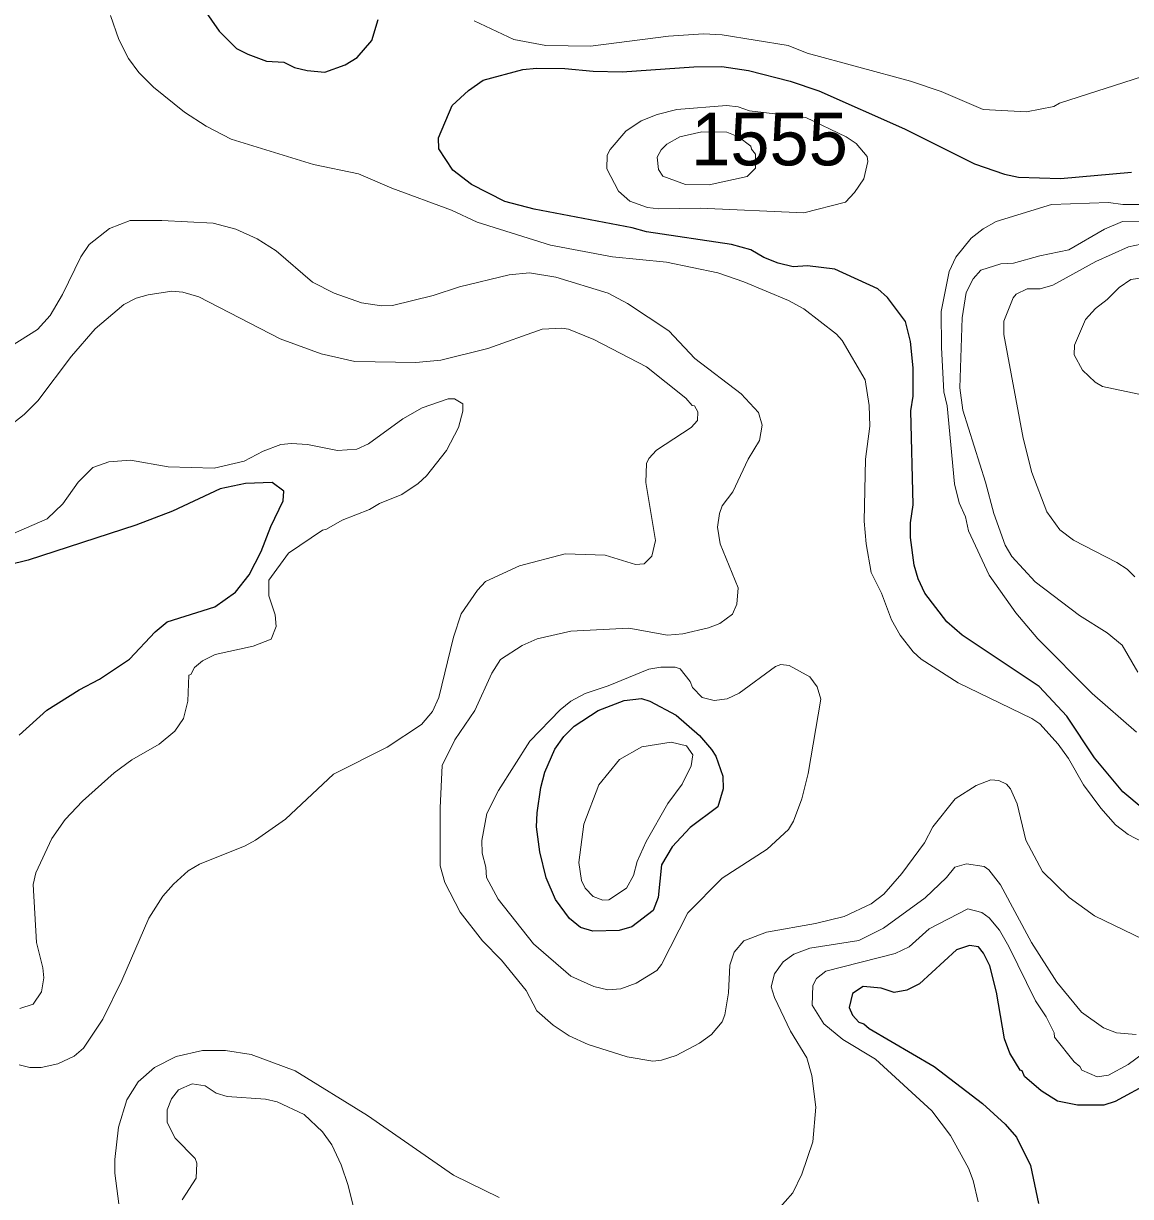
# Model space of a CAD drawing. Extents: x 598.3 to 623.2, y 6902.2 to 6930.1.
# Drawn here: x 605.691 to 607.371, y 6908.921 to 6910.701 of the extents above; entities that cross this region are included whole.
import ezdxf

# ---------------------------------------------------------------- set-up
doc = ezdxf.new("R2010")
doc.units = 0
doc.header["$LTSCALE"] = 0.032
doc.layers.add('1', color=7, linetype='Continuous', lineweight=25)
doc.layers.add('2', color=7, linetype='Continuous', lineweight=13)
doc.layers.add('21', color=7, linetype='Continuous')

msp = doc.modelspace()

# ---------------------------------------------------------------- linework, layer by layer
at = {"layer": '1'}
for points in [[(605.9446, 6910.7518), (605.9877, 6910.6896), (606.0141, 6910.6633), (606.0311, 6910.6543), (606.0598, 6910.644), (606.0857, 6910.6423), (606.1021, 6910.6343), (606.1212, 6910.6295), (606.1482, 6910.627), (606.1788, 6910.6382), (606.1974, 6910.6495), (606.2193, 6910.675), (606.2292, 6910.7071)], [(607.3906, 6909.5092), (607.3598, 6909.5352), (607.3165, 6909.5866), (607.2744, 6909.6497), (607.2324, 6909.695), (607.1155, 6909.7729), (607.0923, 6909.7932), (607.0588, 6909.8364), (607.0487, 6909.8581), (607.0429, 6909.8791), (607.0371, 6909.9212), (607.0371, 6909.9432), (607.0412, 6909.9705), (607.0379, 6910.1132), (607.0411, 6910.1353), (607.0411, 6910.1784), (607.0372, 6910.2184), (607.0297, 6910.2489), (607.0024, 6910.2851), (606.9877, 6910.2983), (606.9226, 6910.3283), (606.8811, 6910.3331), (606.8591, 6910.3317), (606.8364, 6910.3374), (606.8147, 6910.346), (606.795, 6910.3574), (606.7656, 6910.3656), (606.6364, 6910.3849), (606.6146, 6910.3908), (606.4661, 6910.419), (606.4213, 6910.4308), (606.3709, 6910.4566), (606.3424, 6910.4785), (606.321, 6910.5107), (606.3207, 6910.5274), (606.3413, 6910.5767), (606.3662, 6910.5995), (606.3887, 6910.6148), (606.4486, 6910.631), (606.4693, 6910.6334), (606.5125, 6910.6326), (606.5554, 6910.6285), (606.5998, 6910.6278), (606.7083, 6910.6351), (606.7511, 6910.6357), (606.7915, 6910.6295), (606.8546, 6910.6133), (606.8979, 6910.5989), (607.0284, 6910.541), (607.1343, 6910.488), (607.18, 6910.4724), (607.2011, 6910.4676), (607.2652, 6910.4659), (607.3727, 6910.4756)], [(605.6841, 6909.6213), (605.7264, 6909.6591), (605.7753, 6909.6897), (605.8061, 6909.7059), (605.8518, 6909.7366), (605.8907, 6909.7777), (605.9089, 6909.7928), (605.981, 6909.816), (606.0124, 6909.8379), (606.0331, 6909.8642), (606.0514, 6909.8996), (606.0662, 6909.9375), (606.085, 6909.9767), (606.0859, 6909.9912), (606.068, 6910.0045), (606.0279, 6910.0029), (605.9891, 6909.9948), (605.9169, 6909.9612), (605.8612, 6909.9398), (605.6977, 6909.8864), (605.607, 6909.8645)], [(607.4019, 6909.0943), (607.3478, 6909.0649), (607.3306, 6909.0594), (607.2907, 6909.0598), (607.2603, 6909.0656), (607.2356, 6909.0815), (607.2101, 6909.1029), (607.2069, 6909.1115), (607.2038, 6909.1127), (607.1883, 6909.1386), (607.1798, 6909.1601), (607.1677, 6909.2309), (607.1577, 6909.2708), (607.1481, 6909.2903), (607.1403, 6909.2998), (607.1266, 6909.3017), (607.1073, 6909.2951), (607.0511, 6909.2436), (607.0317, 6909.234), (607.0123, 6909.2307), (606.9925, 6909.237), (606.9653, 6909.2395), (606.9491, 6909.2291), (606.944, 6909.2079), (606.949, 6909.1964), (606.9586, 6909.1853), (606.9664, 6909.1829), (606.9746, 6909.1759), (607.0733, 6909.1183), (607.1466, 6909.062), (607.1809, 6909.0308), (607.1983, 6909.0109), (607.2193, 6908.968), (607.2314, 6908.9104)]]:
    msp.add_lwpolyline(points, dxfattribs=at)
msp.add_lwpolyline([(606.4697, 6909.4818), (606.4705, 6909.5033), (606.4761, 6909.5414), (606.4823, 6909.5648), (606.4973, 6909.6), (606.5109, 6909.6191), (606.5267, 6909.6347), (606.5633, 6909.6587), (606.6027, 6909.6735), (606.629, 6909.6766), (606.6415, 6909.6724), (606.6814, 6909.6514), (606.7169, 6909.6203), (606.7353, 6909.5995), (606.7417, 6909.589), (606.7522, 6909.559), (606.7529, 6909.5398), (606.7447, 6909.5124), (606.703, 6909.481), (606.6753, 6909.4516), (606.6592, 6909.4243), (606.6541, 6909.3747), (606.6467, 6909.3552), (606.614, 6909.3303), (606.595, 6909.3247), (606.5551, 6909.3237), (606.5361, 6909.3294), (606.5196, 6909.3427), (606.4986, 6909.3717), (606.4844, 6909.4048), (606.4745, 6909.444)], close=True, dxfattribs=at)
at = {"layer": '2'}
for points in [[(607.39, 6909.4589), (607.3679, 6909.4704), (607.3486, 6909.4849), (607.3262, 6909.5102), (607.2997, 6909.5458), (607.2773, 6909.5854), (607.2614, 6909.6076), (607.2334, 6909.6382), (607.2217, 6909.6462), (607.1097, 6909.7006), (607.0533, 6909.7362), (607.0413, 6909.7476), (607.0218, 6909.7727), (607.0086, 6909.7959), (606.9932, 6909.8364), (606.9776, 6909.8678), (606.97, 6909.9112), (606.9667, 6909.9459), (606.969, 6910.0398), (606.9756, 6910.0897), (606.9747, 6910.1213), (606.9683, 6910.1602), (606.9333, 6910.2201), (606.9251, 6910.2297), (606.8753, 6910.2682), (606.852, 6910.2804), (606.7844, 6910.3092), (606.7446, 6910.3227), (606.6669, 6910.3389), (606.5848, 6910.3468), (606.4906, 6910.3647), (606.3792, 6910.3994), (606.3407, 6910.4179), (606.2497, 6910.4512), (606.1992, 6910.4731), (606.131, 6910.487), (606.006, 6910.5254), (605.9678, 6910.5453), (605.9352, 6910.5666), (605.8882, 6910.6045), (605.8659, 6910.6267), (605.8501, 6910.6479), (605.8356, 6910.6766), (605.8229, 6910.7132)], [(606.3747, 6910.7048), (606.435, 6910.6768), (606.4837, 6910.6675), (606.5516, 6910.6667), (606.6698, 6910.682), (606.7232, 6910.6853), (606.7513, 6910.6836), (606.8516, 6910.6674), (606.8806, 6910.6562), (607.0374, 6910.6134), (607.0838, 6910.5976), (607.1478, 6910.5704), (607.2133, 6910.5671)], [(607.2133, 6910.5671), (607.2549, 6910.5752), (607.2632, 6910.5801), (607.4036, 6910.6253)], [(607.3803, 6909.6256), (607.3128, 6909.6843), (607.2307, 6909.7671), (607.1973, 6909.8068), (607.1567, 6909.8639), (607.1255, 6909.931), (607.1205, 6909.9525), (607.1111, 6909.9736), (607.1043, 6910.0023), (607.093, 6910.1208), (607.0881, 6910.1419), (607.0841, 6910.2095), (607.0836, 6910.2641), (607.0961, 6910.3248), (607.106, 6910.3464), (607.1293, 6910.3752), (607.1478, 6910.3896), (607.1674, 6910.4003), (607.2511, 6910.4261), (607.338, 6910.4295), (607.3596, 6910.4264), (607.395, 6910.4263)], [(605.6709, 6910.2106), (605.7119, 6910.2367), (605.7312, 6910.258), (605.7502, 6910.29), (605.7778, 6910.3467), (605.7904, 6910.3655), (605.8215, 6910.39), (605.8528, 6910.4019), (605.9007, 6910.402), (605.9788, 6910.3979), (606.0129, 6910.389), (606.0457, 6910.3743)], [(607.4335, 6910.4011), (607.3591, 6910.4005), (607.3318, 6910.389), (607.2776, 6910.3575), (607.2338, 6910.3485), (607.1935, 6910.3372), (607.1743, 6910.3363), (607.1438, 6910.3268), (607.1326, 6910.3133), (607.122, 6910.2926), (607.1157, 6910.2542), (607.1124, 6910.1482), (607.1165, 6910.1144), (607.1512, 6910.0048), (607.1638, 6909.9576), (607.181, 6909.9092), (607.1912, 6909.8921), (607.2263, 6909.8537), (607.294, 6909.8025), (607.3356, 6909.7763), (607.3585, 6909.7574), (607.3826, 6909.7166)], [(606.0457, 6910.3743), (606.0744, 6910.3559), (606.1294, 6910.3086), (606.1626, 6910.2916), (606.204, 6910.2769), (606.2343, 6910.2725), (606.2511, 6910.2731), (606.3127, 6910.2883), (606.3525, 6910.3016), (606.4278, 6910.3194), (606.4589, 6910.3226), (606.499, 6910.3161), (606.5784, 6910.2917), (606.6075, 6910.2763), (606.6702, 6910.2345), (606.7099, 6910.1924), (606.7802, 6910.139), (606.8065, 6910.1108), (606.8121, 6910.0913), (606.8081, 6910.0681), (606.791, 6910.0401), (606.7678, 6909.9905), (606.7515, 6909.9691), (606.7473, 6909.9576), (606.7442, 6909.9365), (606.7482, 6909.9116), (606.7756, 6909.8445), (606.7735, 6909.8199), (606.7668, 6909.8048), (606.7479, 6909.7906), (606.7304, 6909.784), (606.6917, 6909.7746), (606.6682, 6909.773), (606.6099, 6909.7834), (606.5217, 6909.7787), (606.4706, 6909.7671), (606.4476, 6909.757), (606.4147, 6909.7357), (606.4019, 6909.7153), (606.376, 6909.6586), (606.3456, 6909.6141), (606.3263, 6909.5751), (606.3231, 6909.5107), (606.3232, 6909.423), (606.3306, 6909.3973), (606.3537, 6909.3523), (606.3874, 6909.3088), (606.4166, 6909.2795), (606.4536, 6909.2336), (606.4699, 6909.2029), (606.4949, 6909.1811), (606.5189, 6909.1648), (606.5477, 6909.1515), (606.607, 6909.1327), (606.646, 6909.1262), (606.6593, 6909.1279), (606.6815, 6909.135), (606.7171, 6909.1536), (606.7353, 6909.1668), (606.7512, 6909.186), (606.7553, 6909.1965), (606.761, 6909.23), (606.7632, 6909.2718), (606.7697, 6909.2916), (606.7842, 6909.3092), (606.8187, 6909.3219), (606.8928, 6909.3351), (606.9365, 6909.346), (606.9774, 6909.3651), (606.9967, 6909.3797), (607.024, 6909.4109), (607.0583, 6909.4579), (607.0714, 6909.482), (607.1051, 6909.5244), (607.1369, 6909.5448), (607.1593, 6909.5535), (607.1712, 6909.5525), (607.183, 6909.5469), (607.1893, 6909.5397), (607.199, 6909.5169), (607.2124, 6909.4615), (607.2377, 6909.4144), (607.2783, 6909.3747), (607.3166, 6909.347), (607.4057, 6909.3041)], [(607.3876, 6910.3663), (607.3684, 6910.3623), (607.3184, 6910.3399), (607.2535, 6910.304), (607.2343, 6910.2984), (607.2144, 6910.2983), (607.1975, 6910.2902), (607.1929, 6910.2847), (607.1789, 6910.2495), (607.1788, 6910.2293), (607.2084, 6910.0718), (607.2213, 6910.0194), (607.244, 6909.9598), (607.2642, 6909.9328), (607.2847, 6909.9168), (607.3506, 6909.8829), (607.3663, 6909.8727), (607.3776, 6909.8614)], [(605.6842, 6909.1206), (605.7004, 6909.1165), (605.7174, 6909.1165), (605.743, 6909.1222), (605.7678, 6909.134), (605.7819, 6909.146), (605.8114, 6909.1899), (605.8401, 6909.249), (605.8809, 6909.3434), (605.9025, 6909.3768), (605.9183, 6909.3949), (605.9407, 6909.415), (605.9578, 6909.4255), (606.0274, 6909.4531), (606.043, 6909.4616), (606.0887, 6909.4938), (606.1614, 6909.5618), (606.2427, 6909.6028), (606.295, 6909.6371), (606.3116, 6909.657), (606.321, 6909.6784), (606.3433, 6909.7697), (606.3553, 6909.8051), (606.3797, 6909.8409), (606.3922, 6909.854), (606.4437, 6909.8781), (606.5131, 6909.896), (606.5735, 6909.8943), (606.6197, 6909.88), (606.6328, 6909.8811), (606.6446, 6909.8925), (606.6501, 6909.9165), (606.6355, 6910.0045), (606.6365, 6910.0333), (606.6398, 6910.041), (606.6517, 6910.0537), (606.7045, 6910.088), (606.7141, 6910.0988), (606.7145, 6910.1117), (606.7094, 6910.1206), (606.7059, 6910.1213), (606.696, 6910.1325), (606.6363, 6910.1801), (606.5565, 6910.2213), (606.518, 6910.2369), (606.5081, 6910.2385), (606.478, 6910.2369), (606.3954, 6910.208), (606.3245, 6910.1899), (606.2861, 6910.1866), (606.1939, 6910.1883), (606.1424, 6910.1999), (606.0802, 6910.2226), (605.9567, 6910.286), (605.9324, 6910.2934), (605.9157, 6910.295), (605.8801, 6910.2894), (605.8619, 6910.2841), (605.8429, 6910.2747), (605.7995, 6910.2378), (605.7638, 6910.1963), (605.7126, 6910.1283), (605.6919, 6910.1075), (605.6661, 6910.0876)], [(605.6851, 6909.2062), (605.7053, 6909.2126), (605.718, 6909.2316), (605.7217, 6909.2527), (605.72, 6909.2681), (605.7104, 6909.3065), (605.7055, 6909.3944), (605.7096, 6909.4122), (605.7339, 6909.464), (605.754, 6909.4929), (605.7805, 6909.521), (605.8282, 6909.5637), (605.855, 6909.5834), (605.8966, 6909.6076), (605.9206, 6909.6272), (605.9336, 6909.6465), (605.9402, 6909.6724), (605.9417, 6909.7122), (605.945, 6909.7133), (605.9503, 6909.7238), (605.9625, 6909.7336), (605.9817, 6909.7434), (606.0393, 6909.756), (606.0667, 6909.7667), (606.0744, 6909.7858), (606.0729, 6909.8037), (606.0633, 6909.8327), (606.0633, 6909.8561), (606.0928, 6909.8972), (606.1446, 6909.9321), (606.1509, 6909.9334), (606.1746, 6909.9473), (606.2162, 6909.9634), (606.231, 6909.9726), (606.2651, 6909.9864), (606.2901, 6910.003), (606.3026, 6910.0147), (606.3328, 6910.0531), (606.3512, 6910.0881), (606.3579, 6910.1127), (606.3579, 6910.124), (606.3449, 6910.1315), (606.3352, 6910.1315), (606.2959, 6910.1176), (606.2667, 6910.1013), (606.2146, 6910.063), (606.1967, 6910.0552), (606.1676, 6910.0531), (606.1218, 6910.0619), (606.0978, 6910.0635), (606.0816, 6910.062), (606.0546, 6910.052), (606.0258, 6910.0368), (605.98, 6910.0264), (605.9106, 6910.028), (605.8534, 6910.0384), (605.8204, 6910.036), (605.7961, 6910.0271), (605.7736, 6910.0052), (605.7507, 6909.9721), (605.7269, 6909.9491), (605.6637, 6909.922)], [(607.3798, 6909.1667), (607.3501, 6909.1691), (607.33, 6909.1769), (607.2968, 6909.2006), (607.2592, 6909.2463), (607.221, 6909.3065), (607.174, 6909.3939), (607.1562, 6909.4165), (607.1491, 6909.4217), (607.1224, 6909.4257), (607.1047, 6909.4209), (607.0918, 6909.405), (607.0594, 6909.3742), (606.9964, 6909.3284), (606.9587, 6909.3095), (606.8844, 6909.2979), (606.8601, 6909.2889), (606.8441, 6909.2771), (606.8306, 6909.2589), (606.8259, 6909.239), (606.8306, 6909.2231), (606.8552, 6909.1718), (606.8801, 6909.1316), (606.8873, 6909.1046), (606.8938, 6909.0563), (606.8888, 6909.0037), (606.8723, 6908.9547), (606.8584, 6908.9267), (606.8238, 6908.8869)], [(607.3909, 6909.1383), (607.3679, 6909.1212), (607.3377, 6909.1052), (607.3208, 6909.1028), (607.2971, 6909.1125), (607.2942, 6909.1184), (607.2859, 6909.1251), (607.2558, 6909.1628), (607.2555, 6909.1692), (607.2433, 6909.1937), (607.2271, 6909.2179), (607.1867, 6909.3005), (607.1722, 6909.3253), (607.1568, 6909.3438), (607.1453, 6909.3521), (607.1245, 6909.3577), (607.0657, 6909.3271), (607.0352, 6909.3001), (607.0141, 6909.2898), (606.9086, 6909.263), (606.8947, 6909.2517), (606.8889, 6909.2413), (606.8881, 6909.2115), (606.9056, 6909.1832), (606.9347, 6909.159), (606.9842, 6909.1296), (607.0694, 6909.0508)], [(606.4129, 6908.9197), (606.3436, 6908.9536), (606.2128, 6909.0438), (606.1032, 6909.1115), (606.0363, 6909.1366), (605.9972, 6909.1423), (605.9627, 6909.1423), (605.9224, 6909.1334), (605.8897, 6909.1168), (605.8648, 6909.0952), (605.8474, 6909.0677), (605.8349, 6909.0264), (605.8294, 6908.977), (605.8294, 6908.9565), (605.8356, 6908.9098)], [(606.1919, 6908.9047), (606.1838, 6908.9379), (606.1729, 6908.9691), (606.1586, 6908.9994), (606.1445, 6909.019), (606.1167, 6909.0452), (606.076, 6909.0647), (606.0579, 6909.0688), (605.9999, 6909.0728), (605.9832, 6909.078), (605.9667, 6909.089), (605.9467, 6909.0921), (605.926, 6909.0827), (605.9153, 6909.069), (605.9087, 6909.0525), (605.9086, 6909.0335), (605.9211, 6909.0097), (605.9511, 6908.9785), (605.9541, 6908.9718), (605.9531, 6908.949), (605.9317, 6908.9158)], [(607.0694, 6909.0508), (607.0979, 6909.0134), (607.1251, 6908.9638), (607.1326, 6908.9455), (607.1399, 6908.9128)]]:
    msp.add_lwpolyline(points, dxfattribs=at)
for points in [[(606.5814, 6910.5097), (606.6053, 6910.5374), (606.6284, 6910.5533), (606.6528, 6910.5628), (606.6823, 6910.5704), (606.7581, 6910.5767), (606.7756, 6910.5743), (606.7929, 6910.5687), (606.8783, 6910.5581), (606.9394, 6910.5289), (606.9549, 6910.5188), (606.9713, 6910.4994), (606.9723, 6910.4918), (606.9666, 6910.4654), (606.9522, 6910.4443), (606.9385, 6910.4297), (606.8754, 6910.4137), (606.7179, 6910.4208), (606.6553, 6910.4198), (606.6382, 6910.4217), (606.6112, 6910.4312), (606.5938, 6910.4468), (606.5764, 6910.4807), (606.5769, 6910.5011)], [(606.7203, 6910.5364), (606.7583, 6910.5363), (606.7759, 6910.5289), (606.7948, 6910.5146), (606.7957, 6910.5102), (606.8021, 6910.5025), (606.802, 6910.4816), (606.7892, 6910.469), (606.7315, 6910.456), (606.6955, 6910.4565), (606.6613, 6910.4693), (606.6546, 6910.4794), (606.6526, 6910.4981), (606.6589, 6910.5093), (606.6674, 6910.5179), (606.6873, 6910.529)], [(607.4599, 6910.1546), (607.4995, 6910.1917), (607.5113, 6910.2099), (607.5138, 6910.2261), (607.5029, 6910.2626), (607.4976, 6910.2732), (607.4829, 6910.2903), (607.4653, 6910.3056), (607.4514, 6910.3111), (607.3971, 6910.3161), (607.3716, 6910.3124), (607.3539, 6910.3003), (607.3359, 6910.2822), (607.3183, 6910.2687), (607.303, 6910.2517), (607.2863, 6910.2131), (607.2856, 6910.1982), (607.2984, 6910.1748), (607.3174, 6910.1565), (607.3285, 6910.1501), (607.3935, 6910.1365), (607.4307, 6910.1414)], [(606.901, 6909.6756), (606.8958, 6909.6943), (606.8843, 6909.7096), (606.853, 6909.7266), (606.8404, 6909.7283), (606.8324, 6909.7251), (606.777, 6909.6846), (606.7588, 6909.6762), (606.7394, 6909.6735), (606.7208, 6909.6782), (606.7062, 6909.6934), (606.7026, 6909.7026), (606.6875, 6909.7217), (606.68, 6909.7243), (606.6585, 6909.7243), (606.6402, 6909.7213), (606.5782, 6909.6959), (606.5435, 6909.6844), (606.5215, 6909.6725), (606.5052, 6909.6596), (606.4592, 6909.6121), (606.4116, 6909.5372), (606.3942, 6909.502), (606.3863, 6909.4611), (606.3869, 6909.4421), (606.3926, 6909.4206), (606.3938, 6909.405), (606.4115, 6909.3723), (606.4647, 6909.3044), (606.5214, 6909.2551), (606.5564, 6909.2398), (606.5779, 6909.2347), (606.5975, 6909.2362), (606.6208, 6909.2446), (606.6523, 6909.2637), (606.6595, 6909.2728), (606.6992, 6909.3515), (606.7516, 6909.404), (606.8198, 6909.4479), (606.8523, 6909.4781), (606.8594, 6909.4906), (606.8721, 6909.5242), (606.8817, 6909.5628)], [(606.6687, 6909.5172), (606.6908, 6909.5469), (606.7045, 6909.5744), (606.7067, 6909.591), (606.6973, 6909.6047), (606.674, 6909.6103), (606.6294, 6909.6035), (606.5955, 6909.5839), (606.5641, 6909.5458), (606.5416, 6909.4858), (606.5336, 6909.4279), (606.538, 6909.4005), (606.5434, 6909.3891), (606.5555, 6909.3764), (606.5704, 6909.3707), (606.5794, 6909.3714), (606.606, 6909.3889), (606.6169, 6909.4079), (606.6225, 6909.4293), (606.6358, 6909.4595)]]:
    msp.add_lwpolyline(points, close=True, dxfattribs=at)

# ---------------------------------------------------------------- texts
at = {"layer": '21'}
msp.add_text('1555', height=0.08, dxfattribs=at).set_placement((606.7042, 6910.4857))

doc.saveas('drawing.dxf')
